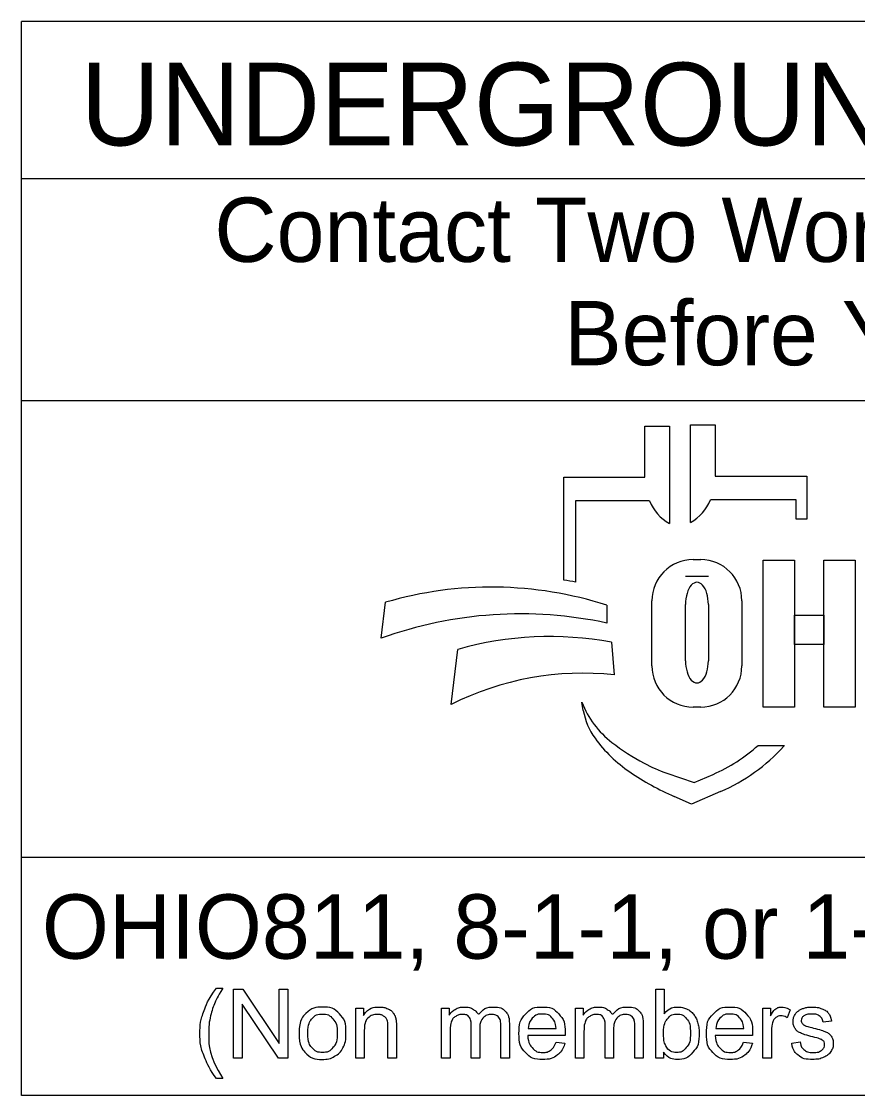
# Model space of a CAD drawing. Extents: x 0 to 29006, y 0 to 889393.
# Drawn here: x 2.378 to 4.196, y 2.143 to 4.48 of the extents above; entities that cross this region are included whole.
import ezdxf

# ---------------------------------------------------------------- set-up
doc = ezdxf.new("R2010")
doc.units = 0
doc.layers.add('SH_Data', color=7, linetype='Continuous')
doc.layers.add('SH_Text', color=7, linetype='Continuous')

msp = doc.modelspace()

# ---------------------------------------------------------------- linework, layer by layer
at = {"layer": 'SH_Data'}
for p, q in [((2.3775, 2.1428), (2.3775, 4.4803)), ((6.6275, 4.4803), (2.3775, 4.4803)), ((2.3775, 4.1387), (6.6275, 4.1387)), ((2.3775, 3.6553), (6.6275, 3.6553)), ((6.6275, 2.6607), (2.3775, 2.6607)), ((6.6275, 2.1428), (2.3775, 2.1428))]:
    msp.add_line(p, q, dxfattribs=at)
at = {"layer": 'SH_Text'}
for p, q in [((3.7335, 3.4883), (3.7335, 3.5998)), ((3.7335, 3.5998), (3.7872, 3.5998)), ((3.7872, 3.5998), (3.7872, 3.3877)), ((3.8329, 3.39), (3.8329, 3.6021)), ((3.8329, 3.6021), (3.8865, 3.6021)), ((3.8865, 3.6021), (3.8865, 3.4906)), ((3.5576, 3.2644), (3.5576, 3.4883)), ((3.5576, 3.4883), (3.7335, 3.4883)), ((3.8865, 3.4906), (4.0857, 3.4906)), ((4.0857, 3.4906), (4.0857, 3.3968)), ((3.5828, 3.4369), (3.5828, 3.26)), ((3.7439, 3.4369), (3.5828, 3.4369)), ((4.0625, 3.4392), (3.8761, 3.4392)), ((4.0625, 3.3968), (4.0625, 3.4392)), ((4.0857, 3.3968), (4.0625, 3.3968)), ((3.8385, 3.3091), (3.8551, 3.3091)), ((3.8718, 3.2721), (3.822, 3.2721)), ((3.1602, 3.1381), (3.1696, 3.2162)), ((3.6509, 3.2097), (3.6509, 3.1709)), ((3.7491, 3.0776), (3.7491, 3.2196)), ((3.822, 3.089), (3.822, 3.2114)), ((3.8718, 3.2114), (3.8718, 3.089)), ((3.9445, 3.2196), (3.9445, 3.0776)), ((3.312, 2.9936), (3.3267, 3.1137)), ((3.6608, 3.1291), (3.6671, 3.0582)), ((3.5997, 2.9807), (3.5967, 2.9986)), ((3.8551, 2.9882), (3.8385, 2.9882)), ((3.98, 2.9048), (4.0375, 2.9048)), ((3.7816, 2.8444), (3.841, 2.8239)), ((3.841, 2.8239), (3.8821, 2.8417)), ((3.835, 2.7769), (3.7976, 2.7934)), ((3.8983, 2.8044), (3.835, 2.7769))]:
    msp.add_line(p, q, dxfattribs=at)
for points in [[(3.991, 3.3081), (4.0589, 3.3081), (4.0589, 2.9881), (3.991, 2.9881)], [(4.1231, 3.3081), (4.1911, 3.3081), (4.1911, 2.9881), (4.1231, 2.9881)], [(4.0589, 3.1882), (4.1231, 3.1882), (4.1231, 3.1242), (4.0589, 3.1242)]]:
    msp.add_lwpolyline(points, close=True, dxfattribs=at)
for points in [[(2.8021, 2.3766), (2.8153, 2.3766)], [(2.8389, 2.2239), (2.8389, 2.3741), (2.8592, 2.3741), (2.9382, 2.2561), (2.9382, 2.3741), (2.9572, 2.3741), (2.9572, 2.2239), (2.9369, 2.2239), (2.8579, 2.3419), (2.8579, 2.2239), (2.8389, 2.2239)], [(3.7743, 2.2239), (3.7573, 2.2239), (3.7573, 2.3741), (3.7757, 2.3741), (3.7757, 2.3206)], [(3.1048, 2.2239), (3.1048, 2.3328), (3.1214, 2.3328), (3.1214, 2.3173)], [(3.2912, 2.2239), (3.2912, 2.3328), (3.3077, 2.3328), (3.3077, 2.3174)], [(3.5826, 2.2239), (3.5826, 2.3328), (3.5991, 2.3328), (3.5991, 2.3174)], [(3.9904, 2.2239), (3.9904, 2.3328), (4.007, 2.3328), (4.007, 2.3163)], [(4.0495, 2.3293), (4.043, 2.3122)], [(3.1932, 2.2908), (3.1932, 2.2239), (3.1748, 2.2239), (3.1748, 2.2901)], [(3.3743, 2.2871), (3.3743, 2.2239), (3.3559, 2.2239), (3.3559, 2.2946)], [(3.4388, 2.2986), (3.4388, 2.2239), (3.4203, 2.2239), (3.4203, 2.2924)], [(3.6657, 2.2871), (3.6657, 2.2239), (3.6473, 2.2239), (3.6473, 2.2946)], [(3.7301, 2.2986), (3.7301, 2.2239), (3.7117, 2.2239), (3.7117, 2.2924)], [(4.1394, 2.3046), (4.1213, 2.3022)], [(3.1233, 2.2833), (3.1233, 2.2239), (3.1048, 2.2239)], [(3.3097, 2.2803), (3.3097, 2.2239), (3.2912, 2.2239)], [(3.56, 2.2736), (3.4788, 2.2736)], [(3.4799, 2.2887), (3.5406, 2.2887)], [(3.601, 2.2803), (3.601, 2.2239), (3.5826, 2.2239)], [(3.968, 2.2736), (3.8868, 2.2736)], [(3.8879, 2.2887), (3.9486, 2.2887)], [(4.0088, 2.2809), (4.0088, 2.2239), (3.9904, 2.2239)], [(3.5404, 2.2591), (3.5595, 2.2567)], [(3.9484, 2.2591), (3.9675, 2.2567)], [(4.053, 2.2564), (4.0712, 2.2593)], [(3.7743, 2.2375), (3.7743, 2.2239)], [(2.8153, 2.1798), (2.8021, 2.1798)]]:
    msp.add_lwpolyline(points, dxfattribs=at)
for centre, radius, start, end in [((3.8353, 3.4736), 0.0985, 201.9296, 240.7469), ((3.7847, 3.476), 0.0985, 299.2531, 338.0704), ((3.8385, 3.2196), 0.0895, 90, 180), ((3.8551, 3.2196), 0.0895, 0, 90), ((3.3997, 2.4302), 0.8191, 72.1402, 106.3144), ((3.4295, 2.4554), 0.8191, 79.2074, 81.0007), ((3.4628, 2.2991), 0.8919, 77.8238, 109.8274), ((3.5267, 2.4094), 0.7322, 79.44, 105.8467), ((3.8385, 3.0776), 0.0895, 180, 270), ((3.8551, 3.0776), 0.0895, 270, 0), ((3.5987, 2.4262), 0.6357, 83.8248, 116.8021), ((3.7841, 3.0707), 0.2008, 201.0457, 232.5314), ((3.741, 3.0048), 0.1433, 189.6817, 216.0884), ((3.8747, 3.1022), 0.3088, 216.0884, 235.7167), ((3.9766, 3.3219), 0.5173, 232.5314, 241.794), ((3.7387, 3.1722), 0.3602, 293.4582, 312.0712), ((3.7387, 3.1722), 0.401, 293.4582, 317.8286), ((3.8914, 3.1631), 0.3371, 241.794, 250.9821), ((4.0412, 3.3465), 0.6044, 235.7167, 246.2325)]:
    msp.add_arc(centre, radius, start, end, dxfattribs=at)
for centre, start_param, end_param in [((3.8469, 3.2114), 4.712389, 7.853982), ((3.8469, 3.089), 1.570796, 4.712389)]:
    msp.add_ellipse(centre, major_axis=(0, 0.0484), ratio=0.514403, start_param=start_param, end_param=end_param, dxfattribs=at)
for points in [[(2.8021, 2.1798), (2.7869, 2.199), (2.7763, 2.2248), (2.7657, 2.2506), (2.7657, 2.2783), (2.7657, 2.3026), (2.7736, 2.325), (2.7829, 2.3509), (2.8021, 2.3766)], [(2.8153, 2.3766), (2.8029, 2.3553), (2.7989, 2.3462), (2.7927, 2.332), (2.7891, 2.3167), (2.7847, 2.2975), (2.7847, 2.2782), (2.7847, 2.2289), (2.8153, 2.1798)], [(2.9814, 2.2783), (2.9814, 2.3085), (2.9981, 2.3231), (3.0122, 2.3352), (3.0323, 2.3352), (3.0547, 2.3352), (3.069, 2.3205), (3.0832, 2.3058), (3.0832, 2.2799), (3.0832, 2.2589), (3.0769, 2.2469), (3.0706, 2.2348), (3.0586, 2.2282), (3.0466, 2.2215), (3.0323, 2.2215), (3.0095, 2.2215), (2.9954, 2.2362), (2.9814, 2.2508), (2.9814, 2.2783)], [(3.0003, 2.2783), (3.0003, 2.2574), (3.0094, 2.247), (3.0185, 2.2366), (3.0323, 2.2366), (3.046, 2.2366), (3.0551, 2.2471), (3.0642, 2.2575), (3.0642, 2.279), (3.0642, 2.2991), (3.0551, 2.3095), (3.0459, 2.3199), (3.0323, 2.3199), (3.0185, 2.3199), (3.0094, 2.3096), (3.0003, 2.2992), (3.0003, 2.2783)], [(3.1214, 2.3173), (3.1334, 2.3352), (3.156, 2.3352), (3.1659, 2.3352), (3.1741, 2.3316), (3.1823, 2.3281), (3.1864, 2.3224), (3.1905, 2.3166), (3.1922, 2.3087), (3.1932, 2.3036), (3.1932, 2.2908)], [(3.1748, 2.2901), (3.1748, 2.3013), (3.1726, 2.3069), (3.1705, 2.3125), (3.165, 2.3158), (3.1595, 2.3191), (3.1521, 2.3191), (3.1404, 2.3191), (3.1318, 2.3117), (3.1233, 2.3042), (3.1233, 2.2833)], [(3.3077, 2.3174), (3.3128, 2.3254), (3.3214, 2.3303), (3.3299, 2.3352), (3.3407, 2.3352), (3.3528, 2.3352), (3.3606, 2.3301), (3.3683, 2.3251), (3.3715, 2.3161), (3.3844, 2.3352), (3.4051, 2.3352), (3.4213, 2.3352), (3.43, 2.3262), (3.4388, 2.3172), (3.4388, 2.2986)], [(3.3559, 2.2946), (3.3559, 2.3069), (3.3514, 2.313), (3.3469, 2.3191), (3.3366, 2.3191), (3.3288, 2.3191), (3.3222, 2.315), (3.3156, 2.311), (3.3126, 2.3031), (3.3097, 2.2952), (3.3097, 2.2803)], [(3.4203, 2.2924), (3.4203, 2.3035), (3.4185, 2.3083), (3.4168, 2.3132), (3.412, 2.3162), (3.4073, 2.3191), (3.401, 2.3191), (3.3895, 2.3191), (3.3819, 2.3115), (3.3743, 2.3039), (3.3743, 2.2871)], [(3.5595, 2.2567), (3.555, 2.24), (3.5428, 2.2307), (3.5306, 2.2215), (3.5117, 2.2215), (3.4878, 2.2215), (3.4738, 2.2362), (3.4598, 2.2509), (3.4598, 2.2774), (3.4598, 2.3049), (3.474, 2.32), (3.4881, 2.3352), (3.5106, 2.3352), (3.5324, 2.3352), (3.5463, 2.3203), (3.5601, 2.3055), (3.5601, 2.2785), (3.5601, 2.2769), (3.56, 2.2736)], [(3.5406, 2.2887), (3.5394, 2.3025), (3.5337, 2.3094), (3.5249, 2.3201), (3.5108, 2.3201), (3.4981, 2.3201), (3.4894, 2.3115), (3.4808, 2.303), (3.4799, 2.2887)], [(3.5991, 2.3174), (3.6042, 2.3254), (3.6127, 2.3303), (3.6212, 2.3352), (3.6321, 2.3352), (3.6442, 2.3352), (3.6519, 2.3301), (3.6597, 2.3251), (3.6628, 2.3161), (3.6758, 2.3352), (3.6965, 2.3352), (3.7127, 2.3352), (3.7214, 2.3262), (3.7301, 2.3172), (3.7301, 2.2986)], [(3.6473, 2.2946), (3.6473, 2.3069), (3.6428, 2.313), (3.6383, 2.3191), (3.628, 2.3191), (3.6202, 2.3191), (3.6136, 2.315), (3.607, 2.311), (3.604, 2.3031), (3.601, 2.2952), (3.601, 2.2803)], [(3.7117, 2.2924), (3.7117, 2.3035), (3.7099, 2.3083), (3.7081, 2.3132), (3.7034, 2.3162), (3.6987, 2.3191), (3.6923, 2.3191), (3.6809, 2.3191), (3.6733, 2.3115), (3.6657, 2.3039), (3.6657, 2.2871)], [(3.7741, 2.2792), (3.7741, 2.2596), (3.7794, 2.2509), (3.7881, 2.2366), (3.8029, 2.2366), (3.815, 2.2366), (3.8238, 2.2471), (3.8326, 2.2576), (3.8326, 2.2784), (3.8326, 2.2998), (3.8241, 2.3099), (3.8157, 2.3201), (3.8038, 2.3201), (3.7917, 2.3201), (3.7829, 2.3096), (3.7741, 2.299), (3.7741, 2.2792)], [(3.7757, 2.3206), (3.7874, 2.3352), (3.8055, 2.3352), (3.8155, 2.3352), (3.8245, 2.3311), (3.8335, 2.3271), (3.8392, 2.3198), (3.845, 2.3124), (3.8483, 2.3021), (3.8516, 2.2918), (3.8516, 2.28), (3.8516, 2.252), (3.8378, 2.2368), (3.8239, 2.2215), (3.8046, 2.2215), (3.7853, 2.2215), (3.7743, 2.2375)], [(3.9675, 2.2567), (3.963, 2.24), (3.9508, 2.2307), (3.9386, 2.2215), (3.9196, 2.2215), (3.8958, 2.2215), (3.8818, 2.2362), (3.8678, 2.2509), (3.8678, 2.2774), (3.8678, 2.3049), (3.882, 2.32), (3.8961, 2.3352), (3.9186, 2.3352), (3.9404, 2.3352), (3.9543, 2.3203), (3.9681, 2.3055), (3.9681, 2.2785), (3.9681, 2.2769), (3.968, 2.2736)], [(3.9486, 2.2887), (3.9474, 2.3025), (3.9417, 2.3094), (3.9328, 2.3201), (3.9188, 2.3201), (3.9061, 2.3201), (3.8974, 2.3115), (3.8888, 2.303), (3.8879, 2.2887)], [(4.007, 2.3163), (4.0133, 2.3278), (4.0187, 2.3315), (4.0241, 2.3352), (4.0305, 2.3352), (4.0398, 2.3352), (4.0495, 2.3293)], [(4.043, 2.3122), (4.0363, 2.3162), (4.0295, 2.3162), (4.0235, 2.3162), (4.0187, 2.3125), (4.0139, 2.3089), (4.0119, 2.3024), (4.0088, 2.2926), (4.0088, 2.2809)], [(4.1213, 2.3022), (4.1201, 2.3106), (4.1142, 2.3153), (4.1083, 2.3201), (4.0975, 2.3201), (4.0848, 2.3201), (4.0794, 2.3159), (4.0739, 2.3116), (4.0739, 2.306), (4.0739, 2.3024), (4.0762, 2.2995), (4.0785, 2.2966), (4.0833, 2.2946), (4.086, 2.2936), (4.0996, 2.2899), (4.1192, 2.2847), (4.1269, 2.2813), (4.1347, 2.278), (4.1391, 2.2717), (4.1435, 2.2653), (4.1435, 2.2559), (4.1435, 2.2467), (4.1381, 2.2386), (4.1327, 2.2304), (4.1226, 2.226), (4.1124, 2.2215), (4.0996, 2.2215), (4.0784, 2.2215), (4.0672, 2.2303), (4.0561, 2.2391), (4.053, 2.2564)], [(4.0712, 2.2593), (4.0727, 2.2483), (4.0798, 2.2425), (4.0868, 2.2366), (4.0995, 2.2366), (4.1122, 2.2366), (4.1184, 2.2418), (4.1245, 2.247), (4.1245, 2.254), (4.1245, 2.2602), (4.1191, 2.2638), (4.1153, 2.2663), (4.1002, 2.2701), (4.0799, 2.2752), (4.072, 2.2789), (4.0642, 2.2827), (4.0601, 2.2893), (4.0561, 2.2959), (4.0561, 2.3038), (4.0561, 2.3111), (4.0594, 2.3173), (4.0628, 2.3235), (4.0685, 2.3276), (4.0728, 2.3308), (4.0803, 2.333), (4.0877, 2.3352), (4.0962, 2.3352), (4.109, 2.3352), (4.1187, 2.3315), (4.1284, 2.3278), (4.133, 2.3215), (4.1377, 2.3152), (4.1394, 2.3046)], [(3.4788, 2.2736), (3.4799, 2.2557), (3.489, 2.2462), (3.4981, 2.2366), (3.5117, 2.2366), (3.5219, 2.2366), (3.5291, 2.242), (3.5362, 2.2473), (3.5404, 2.2591)], [(3.8868, 2.2736), (3.8879, 2.2557), (3.897, 2.2462), (3.9061, 2.2366), (3.9197, 2.2366), (3.9299, 2.2366), (3.937, 2.242), (3.9442, 2.2473), (3.9484, 2.2591)]]:
    msp.add_open_spline(points, degree=3, dxfattribs=at)

# ---------------------------------------------------------------- texts
for s, height, p in [('UNDERGROUND UTILITIES', 0.18, (2.5057, 4.2106)), ('Contact Two Working Days', 0.14, (2.7972, 3.9571)), ('Before You Dig', 0.14, (3.5583, 3.7321)), ('OHIO811, 8-1-1, or 1-800-362-2764', 0.14, (2.422, 2.4406))]:
    msp.add_text(s, height=height, dxfattribs=at).set_placement(p)

doc.saveas('drawing.dxf')
